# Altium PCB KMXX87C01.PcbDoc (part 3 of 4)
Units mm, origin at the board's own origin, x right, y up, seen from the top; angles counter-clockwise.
Board outline 109.2 x 85.1 mm, 4 copper layers (Top Layer, Mid-Layer 1, Mid-Layer 2, Bottom Layer); 294 components, 222 nets, 951 pads, 352 vias.
Unrouted connection lines stored in the file: 266.
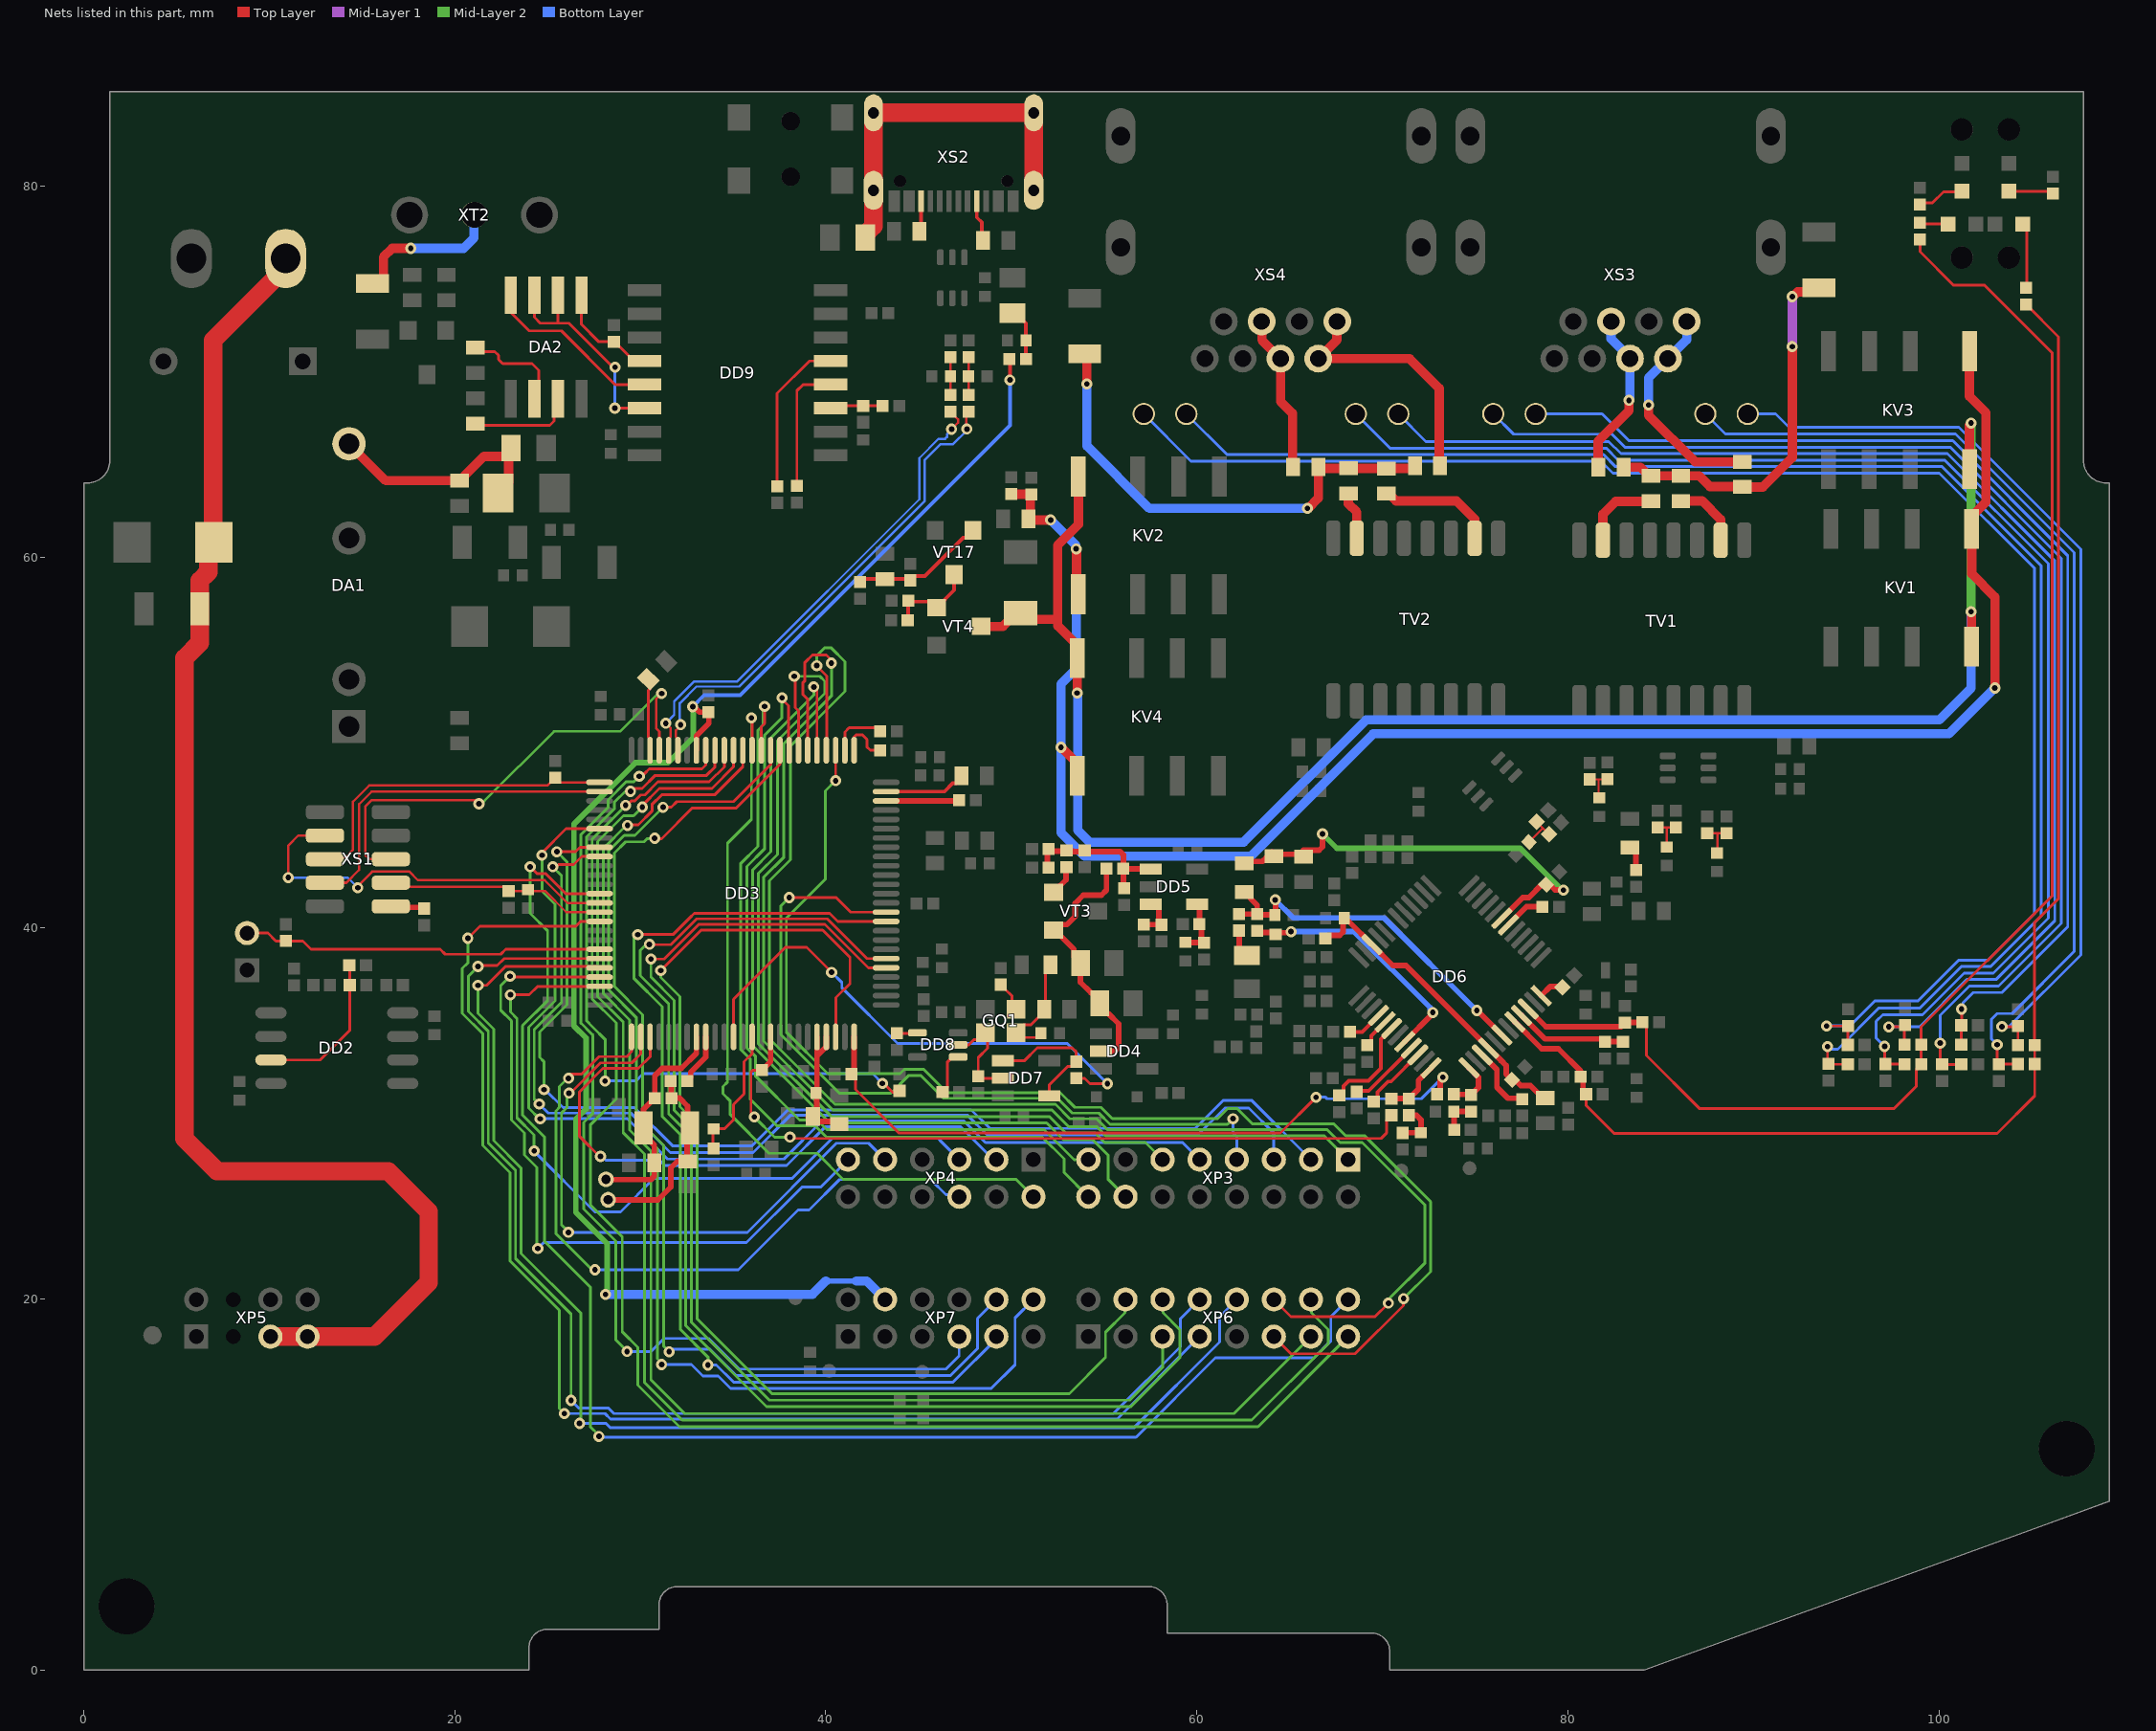
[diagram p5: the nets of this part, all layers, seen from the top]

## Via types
v1: diameter 0.6, hole 0.3, Top Layer to Bottom Layer, tented both sides, 292 vias
v2: diameter 0.6, hole 0.3, Top Layer to Bottom Layer, 60 vias

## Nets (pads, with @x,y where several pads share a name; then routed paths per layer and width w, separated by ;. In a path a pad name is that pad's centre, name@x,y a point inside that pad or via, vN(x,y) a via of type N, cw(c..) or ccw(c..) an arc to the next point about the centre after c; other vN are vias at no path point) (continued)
JTCK-SWCLK: DD3.76 R7.2 XS1.6 | length 18.2
  Top Layer w0.13: XS1.6@13,43.715 13.081,43.796 14.09,43.796 14.509,44.215 14.509,46.815 15.381,47.687 24.994,47.687 R7.2@25.407,48.1 25.649,47.857 DD3.76@27.8,47.857
JTDI: DD3.77 XS1.4 | length 18.9
  Top Layer w0.13: XS1.4@13,42.445 14.145,42.445 14.839,43.139 14.839,46.679 15.518,47.357 DD3.77@27.8,47.357
JTDO/SWO: DD3.89 XS1.8 | length 22
  Top Layer w0.13: v1(11.025,42.725) 11.025,44.45 11.56,44.985 XS1.8@13,44.985 ; v1(14.77,42.175) 14.77,42.263 15.547,43.04 17.553,43.04 18.007,42.585 24.841,42.585 26.085,41.341 27.784,41.341 DD3.89@27.8,41.357
  Bottom Layer w0.13: v1(11.025,42.725) 14.22,42.725 v1(14.77,42.175)
JTMS-SWDIO: DD3.72 XS1.5 | length 26
  Top Layer w0.13: XS1.5@16.55,43.715 15.385,43.715 15.169,43.931 15.169,46.542 15.527,46.9 21.1,46.9 v1(21.3,46.7) ; DD3.72@31.025,49.582 31.025,50.593 30.861,50.757 30.861,52.361 v1(31.15,52.65)
  Mid-Layer 2 w0.13: v1(21.3,46.7) 21.427,46.7 21.572,46.845 21.595,46.845 25.35,50.6 28.912,50.6 30.872,52.56 31.06,52.56 v1(31.15,52.65)
MDC: DD3.16 R12.1 R270.2 | length 40.6
  Top Layer w0.15: v1@35.965,29.964 35.965,32.243 36.061,32.34 R12.1@36.565,32.34 ; v1@38.063,28.66 69.929,28.66 70.241,28.971 70.241,29.661 R270.2@70.487,29.907
  Top Layer w0.3: R12.1@36.565,32.34 37.025,32.801 DD3.16@37.025,34.132
  Mid-Layer 2 w0.15: v1(36.145,29.816) 37.233,28.728 v1(38.063,28.728)
MDIO: DD3.25 R11.1 R271.2 | length 37.5
  Top Layer w0.15: R11.1@41.375,32.125 41.598,31.903 41.598,31.297 43.935,28.96 64.505,28.96 v1(66.424,30.879)
  Top Layer w0.3: 41.525,32.495 DD3.25@41.525,34.132 ; R271.2@72.954,31.046 73.121,31.214 73.121,31.823 v1(73.263,31.964)
  Bottom Layer w0.15: v1(66.424,30.879) 66.938,30.879 67.018,30.8 72.099,30.8 v1(73.263,31.964)
NetBQ1_1: BQ1.1 BQ2.2 C8.1 R16.2 R329.2 | length 10.7
  Top Layer w0.3: BQ2.2@28.265,25.35 30.944,25.35 31.639,26.045 31.639,27.069 32,27.43 C8.1@32.3,27.43 ; R16.2@31.675,31.758 R329.2@31.675,30.833 32.117,30.833 32.551,30.399 32.551,29.31 32.655,29.205 BQ1.1@32.764,29.096 ; C8.1@32.525,27.503 32.525,29.075 BQ1.1@32.675,29.225
NetBQ1_2: BQ1.2 BQ2.1 C7.1 DD3.8 R329.1 | length 12.3
  Top Layer w0.3: BQ2.1@28.15,26.454 28.164,26.44 30.574,26.44 30.75,26.616 C7.1@30.75,27.347 ; C7.1@30.755,27.35 30.75,27.355 30.75,28.299 30.574,28.475 30.523,28.475 30.173,28.825 30.173,30.231 30.6,30.658 R329.1@30.775,30.833 30.775,32.038 31.169,32.433 32.208,32.433 33.025,33.25 DD3.8@33.025,34.132
NetC11_1: C11.1 DA1.7 L5.1 L6.1 | length 12.3
  Top Layer w0.5: DA1.7@14.291,66.107 16.276,64.122 C11.1@20.262,64.122 ; C11.1@20.512,64.372 21.566,65.425 22.457,65.425 22.75,65.425 22.787,65.463 22.787,65.638 L5.1@23.025,65.875 ; L6.1@22.326,63.45 22.9,64.024 L5.1@22.9,65.525
NetC17_1: C17.1 DD3.73 | length 4
  Top Layer w0.15: C17.1@30.437,53.46 30.52,53.377 30.52,52.907 30.437,52.824 30.437,50.286 30.525,50.198 DD3.73@30.525,49.582
NetC19_1: C19.1 C22.1 DD3.21 DD3.22 L1.1 | length 7.4
  Top Layer w0.3: C22.1@39.046,29.8 C22.1@39.191,29.945 ; C22.1@39.096,29.75 39.271,29.575 40.307,29.575 L1.1@40.468,29.414 ; C22.1@39.305,29.85 39.513,30.058 39.513,31.062 C19.1@39.475,31.1 39.525,31.15 39.525,33.11 ; DD3.21@39.525,34.132 39.525,33.11 ; DD3.22@40.025,34.132 40.025,33.557 39.973,33.557 39.525,33.11
NetC20_1: C20.1 DD3.49 | length 4.5
  Top Layer w0.2: DD3.49@43.25,47.357 46.395,47.357 46.841,47.804 47.041,47.804 47.316,48.079 C20.1@47.316,48.204
NetC33_1: C33.1 DD3.14 R35.1 | length 7.2
  Top Layer w0.15: C33.1@33.92,29.154 33.92,28.149 R35.1@33.95,28.119 ; C33.1@33.954,29.178 34.537,29.178 35.02,29.66 35.02,30.485 35.596,31.062 35.596,32.796 36.025,33.225 DD3.14@36.025,34.132
NetC36_1: C36.1 DD5.4 R28.2 R33.1 | length 3.1
  Top Layer w0.3: C36.1@59.376,39.225 59.382,39.219 R28.2@60.25,39.219 ; DD5.4@60.016,41.282 60.141,41.157 R33.1@60.141,40.206 60.25,40.097 60.25,39.35 R28.2@60.4,39.2
NetC41_2: C41.2 C150.2 DD4.2 R45.2 VT3.2 | length 13.3
  Top Layer w0.3: C41.2@54.288,36.519 53.729,37.078 C150.2@53.729,38.104 53.371,38.462 53.371,38.856 52.639,39.588 52.332,39.895 VT3.2@52.281,39.895 52.569,40.183 52.995,40.183 53.447,40.635 53.447,41.339 53.878,41.771 54.857,41.771 55.125,42.039 R45.2@55.125,43.207 ; C41.2@54.76,35.746 55.118,35.388 55.237,35.388 55.785,34.84 55.785,33.539 55.609,33.363 DD4.2@54.835,33.363
NetC45_1: C45.1 C47.1 C171.1 DD6.22 DD6.40 R70.2 | length 17.1
  Top Layer w0.3: R70.2@66.929,39.436 67.104,39.611 67.708,39.611 67.884,39.786 67.884,40.477 C45.1@67.943,40.537 67.943,40.512 68.093,40.362 68.192,40.362 DD6.22@69.443,39.111 70.569,37.984 71.276,37.984 72.104,37.156 DD6.40@75.736,33.525 76.403,32.857 76.676,32.585 76.676,32.12 C47.1@76.983,31.813 77.157,31.813 77.462,31.507 77.985,31.507 78.655,30.837 C171.1@78.881,30.837
NetC46_1: C46.1 C48.1 C170.1 DD6.7 L2.1 | length 23.6
  Top Layer w0.3: L2.1@62.55,43.59 63.538,43.59 63.736,43.788 63.803,43.788 64.057,44.041 C170.1@64.057,44.109 ; C170.1@64.153,44.013 64.186,43.98 C46.1@65.746,43.98 ; C46.1@65.746,44.205 66.599,44.205 66.775,44.381 v1(66.775,45.075) ; DD6.7@76.443,40.525 77.568,41.65 77.903,41.65 78.604,42.35 78.816,42.35 C48.1@78.829,42.337 79.033,42.337 79.314,42.057 79.754,42.057 v1(79.764,42.046)
  Mid-Layer 2 w0.3: v1(66.775,45.075) 67.544,44.306 77.435,44.306 79.695,42.046 v1(79.764,42.046)
NetC51_1: C51.1 DD6.42 L2.2 R64.1 R73.1 | length 19.8
  Top Layer w0.3: R73.1@62.28,40.764 62.287,40.757 63.243,40.757 R64.1@63.25,40.75 ; L2.2@62.475,42.012 62.704,42.012 62.9,41.815 62.9,41.587 63.25,41.237 R64.1@63.25,40.75 ; v1(64.227,41.522) 64.243,41.506 64.243,40.734 C51.1@64.202,40.693 64.174,40.722 63.278,40.722 R64.1@63.25,40.75 ; v1(75.092,35.555) 75.12,35.555 DD6.42@76.443,34.232
  Bottom Layer w0.3: v1(64.227,41.522) 65.199,40.55 70.089,40.55 75.084,35.555 v1(75.092,35.555)
NetC52_2: C52.2 R73.2 | length 1.6
  Top Layer w0.3: R73.2@62.28,39.864 62.28,38.882 62.638,38.524 C52.2@62.7,38.524
NetC53_1: C53.1 R92.2 R93.2 | length 2
  Top Layer w0.127: C53.1@77.904,44.645 78.625,45.367 78.625,45.409 ; R92.2@78.31,45.724 78.625,45.409 ; R93.2@78.986,45.056 78.978,45.056 78.625,45.409
NetC54_1: C54.1 R94.2 R95.2 | length 2
  Top Layer w0.127: R94.2@81.183,48.016 81.658,48.016 ; C54.1@81.689,47.024 81.658,47.056 81.658,48.016 ; R95.2@82.139,48.029 82.125,48.016 81.658,48.016
NetC55_1: C55.1 R88.2 R89.2 | length 2
  Top Layer w0.127: R88.2@84.851,45.43 84.852,45.428 85.345,45.428 ; C55.1@85.331,44.372 85.331,45.414 85.345,45.428 ; R89.2@85.82,45.428 85.345,45.428
NetC56_1: C56.1 R90.2 R91.2 | length 2.1
  Top Layer w0.127: R90.2@87.514,45.11 88.06,45.11 ; C56.1@88.035,44.046 88.06,44.071 88.06,45.11 ; R91.2@88.559,45.11 88.06,45.11
NetC61_1: C61.1 KV1.1 KV2.1 KV3.1 KV4.1 R102.2 R103.2 | length 100.5
  Top Layer w0.5: R102.2@50,63.4 50.01,63.39 51.063,63.39 R103.2@51.072,63.381 51.025,63.333 51.025,62.152 C61.1@50.924,62.051 50.975,62 v2(52.12,62) ; v2(52.675,49.747) 52.689,49.747 53.557,48.879 KV4.1@53.557,48.204 ; v2(53.496,60.441) 53.515,60.422 53.515,58.098 KV2.1@53.617,57.995 KV2.1@53.617,57.32 ; KV3.1@101.65,71.1 101.65,68.666 102.545,67.771 102.545,62.969 101.775,62.199 KV1.1@101.775,61.524 101.775,59.1 103.025,57.85 v2@103.025,52.95
  Bottom Layer w0.5: v2(52.12,62) 53.477,60.643 53.477,60.46 v2(53.496,60.441) 53.496,53.971 52.675,53.15 v2(52.675,49.747) 52.675,45.15 53.95,43.875 62.9,43.875 69.5,50.475 100.55,50.475 v2(103.021,52.946)
NetC62_1: C62.1 R25.1 R40.1 R98.1 R99.1 | length 20.5
  Top Layer w0.5: R25.1@83.005,64.85 83.901,64.85 84.364,64.386 R98.1@84.489,64.386 R99.1@86.095,64.386 87.074,64.386 87.66,63.8 R40.1@89.403,63.8 ; R40.1@89.4,63.777 89.403,63.78 90.51,63.78 92.1,65.37 v2(92.1,71.35) ; v2(92.1,74.044) 92.127,74.044 92.386,74.303 93.309,74.303 C62.1@93.525,74.519
  Mid-Layer 1 w0.5: v2(92.1,71.35) v2(92.1,74.044)
NetC63_1: C63.1 R100.1 R101.1 R106.1 R107.1 | length 25.6
  Top Layer w0.5: C63.1@53.954,70.957 54.072,70.84 v2(54.072,69.338) ; v2@66,62.625 66.553,63.178 R106.1@66.553,64.86 66.627,64.786 R100.1@68.172,64.786 68.176,64.782 70.22,64.782 R101.1@70.223,64.778 R107.1@71.389,64.778
  Bottom Layer w0.5: v2(54.072,69.338) 54.072,65.998 57.445,62.625 v2(65.96,62.625)
NetC67_2: C67.2 VD5.1 XP1.1 XP5.5 XP5.7 | length 79.1
  Top Layer w1: XP5.5@10.06,17.976 XP5.7@12.06,17.976 15.677,17.976 18.592,20.891 18.592,24.709 16.411,26.89 7.184,26.89 5.425,28.649 5.425,54.55 6.243,55.368 6.243,57.192 C67.2@6.251,57.2 6.251,58.734 6.708,59.192 6.708,60.495 VD5.1@7.005,60.792 6.975,60.822 6.975,71.695 10.88,75.6 XP1.1@10.88,76.1
  Mid-Layer 1 w1: XP1.1@10.88,75.6 XP1.1@10.88,76.1
  Mid-Layer 2 w2: XP1.1@10.88,75.546 XP1.1@10.88,76.1
NetC74_1: C74.1 L8.2 R8.1 | length 3.1
  Top Layer w0.2: L8.2@49.894,73.158 L8.2@50.069,73.158 50.244,73.158 50.789,72.613 C74.1@50.789,71.672 C74.1@50.789,71.622 ; C74.1@50.714,71.622 C74.1@50.789,71.622 ; R8.1@50.789,70.677 C74.1@50.789,71.622
NetC75_2: C75.2 R3.1 R380.2 | length 2
  Top Layer w0.127: R3.1@47.69,68.738 C75.2@47.69,69.738 R380.2@47.69,70.788
NetC76_2: C76.2 R10.1 R381.2 | length 2
  Top Layer w0.127: R10.1@46.715,68.738 C76.2@46.715,69.738 R381.2@46.715,70.788
NetC102_1: C102.1 R34.2 R322.1 VT17.1 | length 7.4
  Top Layer w0.2: R34.2@41.792,58.714 R34.2@41.847,58.659 ; R34.2@41.811,58.815 C102.1@43.181,58.815 44.481,58.815 R322.1@44.551,58.745 44.776,58.97 45.337,58.97 47.403,61.036 47.574,61.036 47.931,61.393 VT17.1@47.931,61.444
NetC120_1: C120.1 C146.1 GQ1.4 L11.2 | length 6.2
  Top Layer w0.15: C120.1@51.6,34.328 51.6,34.325 51.375,34.1 50.518,34.1 GQ1.4@50.25,34.368 50.675,34.793 51.063,34.793 51.77,35.5 C146.1@51.77,35.625 51.83,35.685 51.83,37.728 L11.2@52.12,38.018
NetC122_1: C122.1 R268.1 R383.2 | length 2.4
  Top Layer w0.3: R268.1@71.091,28.956 71.099,28.964 72.074,28.964 C122.1@72.081,28.971 72.081,29.668 71.842,29.907 R383.2@71.437,29.907
NetC124_1: C124.1 R269.1 R400.2 | length 1.9
  Top Layer w0.3: R269.1@73.872,29.132 73.867,29.137 73.867,30.103 C124.1@73.862,30.107 R400.2@74.793,30.109
NetC125_1: C125.1 DD6.32 R64.2 | length 13.7
  Top Layer w0.3: R64.2@63.2,39.864 63.306,39.758 64.15,39.758 C125.1@64.249,39.66 64.338,39.749 65.021,39.749 v1(65.08,39.808) ; DD6.32@71.21,33.878 72.723,35.391 v1(72.723,35.45)
  Bottom Layer w0.3: v1(65.08,39.808) 65.081,39.807 68.484,39.807 72.581,35.709 72.581,35.614 72.723,35.472 v1(72.723,35.45)
NetDA2_1: DA2.1 DD9.12 R17.1 | length 6
  Top Layer w0.15: DA2.1@26.83,74.344 26.83,72.542 27.763,71.609 R17.1@28.575,71.609 28.825,71.359 28.87,71.359 29.656,70.573 DD9.12@30.234,70.573
NetDA2_2: DA2.2 DA2.3 DD9.14 | length 12.3
  Top Layer w0.15: DA2.3@24.29,74.344 24.29,72.93 24.607,72.613 25.56,72.613 ; DA2.2@25.56,74.344 25.56,72.613 ; v2@28.546,70.278 28.484,70.278 26.149,72.613 25.56,72.613 ; v2(28.624,68.033) DD9.14@30.234,68.033
  Bottom Layer w0.15: v2(28.624,68.033) 28.629,68.039 28.629,70.235 v2(28.635,70.241)
NetDA2_4: DA2.4 DD9.13 | length 10
  Top Layer w0.15: DA2.4@23.02,74.344 23.02,73.183 24.003,72.2 25.745,72.2 28.642,69.303 DD9.13@30.234,69.303
NetDA2_6: DA2.6 R26.2 | length 5.7
  Top Layer w0.15: R26.2@21.106,71.299 21.33,71.075 22.158,71.075 22.354,70.879 22.354,70.653 22.582,70.425 24.166,70.425 24.525,70.066 24.525,68.766 DA2.6@24.29,68.531
NetDA2_7: DA2.7 R18.2 | length 5.7
  Top Layer w0.15: R18.2@21.1,67.205 21.205,67.1 25.117,67.1 25.35,67.333 25.35,68.321 DA2.7@25.56,68.531
NetDD2_7: DD2.7 R326.1 R327.2 | length 8.4
  Top Layer w0.15: DD2.7@10.09,32.889 12.739,32.889 14.336,34.486 R326.1@14.336,36.925 14.336,37.975 R327.2@14.311,38
NetDD3_9: DD3.9 R16.1 | length 2.8
  Top Layer w0.3: R16.1@32.539,31.758 32.714,31.933 32.714,32.229 33.525,33.04 DD3.9@33.525,34.132
NetDD3_12: DD3.12 R169.1 | length 28.3
  Top Layer w0.15: DD3.12@35.025,34.132 35.025,36.159 37.822,38.956 38.972,38.956 v1(40.311,37.617) ; R169.1@53.5,31.9 53.95,31.9 54.237,31.613 v1(55.177,31.613)
  Bottom Layer w0.15: v1(40.311,37.617) 40.864,37.064 40.864,36.786 43.875,33.775 53.016,33.775 v1(55.177,31.613)
NetDD3_48: DD3.48 R200.1 | length 3.9
  Top Layer w0.3: DD3.48@43.25,46.857 47.149,46.857 R200.1@47.183,46.892
NetDD3_51: DD3.51 R201.1 | length 2.8
  Top Layer w0.15: DD3.51@41.525,49.582 41.525,50.3 41.65,50.425 41.966,50.425 42.225,50.166 42.225,49.757 42.4,49.582 R201.1@42.92,49.582
NetDD3_52: DD3.52 R202.1 | length 3.1
  Top Layer w0.15: DD3.52@41.025,49.582 41.025,50.575 41.257,50.807 42.722,50.807 R202.1@42.929,50.6
NetDD3_66: DD3.66 R317.1 | length 39.8
  Top Layer w0.15: v1(29.47,47.372) 29.47,47.439 29.558,47.527 30.1,47.527 30.805,48.232 33.568,48.232 34.025,48.689 DD3.66@34.025,49.582 ; v2(43.05,31.625) 43.128,31.625 43.614,31.139 R317.1@43.99,31.139
  Mid-Layer 2 w0.15: v1(28.1,31.758) 28.1,33.999 27.447,34.652 27.1,34.999 27.1,44.917 28.592,46.409 28.592,46.782 29.264,47.453 29.335,47.382 29.46,47.382 v1(29.47,47.372)
  Bottom Layer w0.15: v1(28.1,31.758) 29.759,31.758 30.151,32.15 42.525,32.15 v2(43.05,31.625)
NetDD3_94: DD3.94 R20.1 XP2.2 | length 19.6
  Top Layer w0.15: XP2.2@8.8,39.729 9.928,39.729 10.356,39.302 R20.1@10.9,39.302 11.806,39.302 12.25,38.857 19.213,38.857 19.482,38.588 22.472,38.588 22.741,38.857 DD3.94@27.8,38.857
NetDD5_1: DD5.1 R44.2 R45.1 R46.1 R47.2 R48.2 R328.2 | length 8.4
  Top Layer w0.3: R44.2@51.964,43.229 51.945,43.248 51.945,44.154 51.948,44.151 52.976,44.151 53.342,44.151 53.364,44.129 53.954,44.129 55.862,44.129 56.038,43.954 R45.1@56.038,43.195 ; R328.2@56.075,42.15 56.05,42.175 56.05,43.182 R45.1@56.038,43.195 ; DD5.1@57.516,43.182 57.504,43.195 R45.1@56.038,43.195
NetDD5_3: DD5.3 R30.2 R41.1 | length 2.5
  Top Layer w0.3: R30.2@57.147,40.186 57.975,40.186 58.122,40.186 58.114,40.186 57.95,40.35 57.95,41.132 57.8,41.282 DD5.3@57.516,41.282
NetDD6_6: DD6.6 R65.1 | length 2.2
  Top Layer w0.3: DD6.6@76.797,40.171 77.775,41.15 R65.1@78.625,41.15
NetDD6_28: DD6.28 R233.1 | length 1.9
  Top Layer w0.2: R233.1@68.25,34.404 68.908,34.404 DD6.28@69.796,35.292
NetDD6_29: DD6.29 R234.1 | length 1.7
  Top Layer w0.2: R234.1@69.183,33.684 69.408,33.909 69.408,34.197 DD6.29@70.15,34.939
NetDD6_30: DD6.30 R51.1 | length 5.4
  Top Layer w0.2: R51.1@67.679,30.971 67.904,31.196 67.904,31.479 68.198,31.773 69.256,31.773 69.925,32.442 69.925,34.007 DD6.30@70.503,34.585
NetDD6_33: DD6.33 R50.1 | length 3.9
  Top Layer w0.2: R50.1@68.61,31.175 68.66,31.225 69.264,31.225 DD6.33@71.564,33.525
NetDD6_34: DD6.34 R321.1 | length 3.6
  Top Layer w0.2: R321.1@69.537,30.65 69.735,30.848 69.735,31.161 70.304,31.73 70.476,31.73 DD6.34@71.917,33.171
NetDD6_36: DD6.36 R270.1 R383.1 | length 3.1
  Top Layer w0.3: R270.1@70.487,30.807 R383.1@71.437,30.807 71.948,31.319 71.948,31.788 DD6.36@72.625,32.464
NetDD6_37: DD6.37 R271.1 R400.1 | length 2.8
  Top Layer w0.3: R271.1@73.854,31.046 73.872,31.027 74.774,31.027 R400.1@74.793,31.009 75.176,31.392 75.176,31.963 DD6.37@74.675,32.464
NetDD6_39: DD6.39 R67.2 | length 3.7
  Top Layer w0.3: DD6.39@75.382,33.171 76.176,32.377 76.176,31.419 76.774,30.82 77.499,30.82 R67.2@77.537,30.782
NetDD6_48: DD6.48 R68.2 | length 1.4
  Top Layer w0.3: DD6.48@78.564,36.353 79.067,36.855 79.411,36.855 79.639,36.627 R68.2@79.658,36.627
NetDD7_1: DD7.1 DD7.4 R169.2 | length 7.4
  Top Layer w0.15: DD7.1@49.634,32.84 50.695,32.84 51.405,33.55 53.272,33.55 53.5,33.322 R169.2@53.5,32.8 53.25,32.55 53.05,32.55 52.05,31.55 DD7.4@52.05,30.95 ; DD7.4@52.134,30.94 DD7.4@52.134,30.95
NetDD7_2: DD7.2 DD8.2 GQ1.3 R357.2 | length 5.8
  Top Layer w0.15: DD8.2@47.138,33.704 47.704,33.704 47.975,33.975 48.27,33.975 GQ1.3@48.483,34.188 ; GQ1.3@48.483,34.25 GQ1.3@48.6,34.368 48.725,34.243 48.725,33.521 48.217,33.013 R357.2@48.217,32.002 48.328,31.89 DD7.2@49.634,31.89
NetDD8_1: DD8.1 R378.1 | length 2.4
  Top Layer w0.15: R378.1@46.294,31.157 46.544,31.407 46.544,32.76 46.838,33.054 DD8.1@47.138,33.054
NetDD8_4: DD8.4 R358.2 | length 1.3
  Top Layer w0.15: R358.2@43.835,34.328 DD8.4@45.117,34.328
NetDD9_3: DD9.3 R4.2 R15.2 | length 2.8
  Top Layer w0.15: DD9.3@40.267,68.033 40.39,68.156 R15.2@42.015,68.156 R4.2@43.05,68.156
NetDD9_4: DD9.4 R5.2 | length 7.1
  Top Layer w0.15: R5.2@38.441,63.835 38.441,68.97 38.774,69.303 DD9.4@40.267,69.303
NetDD9_5: DD9.5 R6.2 | length 8.6
  Top Layer w0.15: R6.2@37.375,63.825 37.375,68.825 39.123,70.573 DD9.5@40.267,70.573
NetGQ1_1: GQ1.1 R167.1 | length 1.7
  Top Layer w0.15: R167.1@49.425,36.95 49.675,36.7 50.025,36.35 50.025,35.843 GQ1.1@50.25,35.618
NetHL1_C: HL1.C R38.2 | length 2.4
  Top Layer w0.15: HL1.C@103.779,79.726 106.031,79.726 R38.2@106.15,79.607
NetHL2_C: HL2.C R37.1 | length 2.4
  Top Layer w0.15: R37.1@99.082,79.107 99.665,79.107 100.248,79.69 101.203,79.69 HL2.C@101.239,79.726
NetHL15_C: HL15.C R74.2 | length 3.6
  Top Layer w0.15: HL15.C@104.529,77.956 104.75,77.735 104.75,74.55 R74.2@104.65,74.45
NetHL16_C: HL16.C R75.2 | length 1.5
  Top Layer w0.15: R75.2@98.983,78.025 99.052,77.956 HL16.C@100.489,77.956
NetKV1_8: KV1.8 KV2.8 KV3.8 KV4.8 VD8.2 VT4.3 | length 96.5
  Top Layer w0.5: VT4.3@48.363,56.265 49.54,56.265 50.25,56.975 VD8.2@50.5,56.975 50.825,56.65 52.498,56.65 ; v2(53.55,52.673) 53.554,52.677 53.554,54.55 KV4.8@53.557,54.554 53.557,55.229 52.498,56.288 52.498,56.65 ; KV2.8@53.617,64.345 53.617,61.767 52.498,60.648 52.498,56.65 ; KV3.8@101.65,64.075 KV3.8@101.65,64.75 101.65,67.109 101.739,67.198 v2(101.739,67.225) ; v2(101.739,57.057) 101.757,57.039 101.757,55.192 KV1.8@101.775,55.174 KV1.8@101.775,54.499
  Mid-Layer 2 w0.5: v2(101.739,57.057) v2(101.739,67.225)
  Bottom Layer w0.5: v2@53.575,52.725 53.575,45.275 54.225,44.625 62.525,44.625 69.125,51.225 100.025,51.225 101.739,52.939 v2(101.739,57.057)
NetL3_1: L3.1 R72.2 | length 1.4
  Top Layer w0.3: L3.1@83.35,44.35 83.45,44.35 83.675,44.125 R72.2@83.675,43.125
NetL4_1: L4.1 XS2.SHELL | length 19.7
  Top Layer w1: L4.1@42.125,77.225 42.125,77.4 42.57,77.845 XS2.SHELL@42.57,79.77 XS2.SHELL@42.57,83.95 XS2.SHELL@51.21,83.95 XS2.SHELL@51.21,79.77
NetR1_1: R1.1 XS2.A5 | length 2.3
  Top Layer w0.2: XS2.A5@48.14,79.195 48.14,78.313 48.403,78.05 48.403,77.154 R1.1@48.475,77.082
NetR2_1: R2.1 XS1.1 | length 1.9
  Top Layer w0.3: XS1.1@16.55,41.175 16.612,41.112 18.288,41.112 R2.1@18.35,41.05
NetR23_1: R23.1 XS2.B5 | length 1.7
  Top Layer w0.2: R23.1@45.045,77.563 45.14,77.658 XS2.B5@45.14,79.195
NetR25_2: R25.2 XS3.4 XS3.5 | length 8
  Top Layer w0.5: R25.2@81.645,64.85 81.635,64.86 81.635,66.24 83.3,67.905 v2(83.3,68.45)
  Bottom Layer w0.5: XS3.4@82.33,72.202 82.33,71.77 83.35,70.75 XS3.5@83.35,70.7 ; v2(83.3,68.45) 83.35,68.5 XS3.5@83.35,70.202
NetR40_2: R40.2 XS3.7 XS3.8 | length 11.2
  Top Layer w0.5: v2(84.35,68.202) 84.35,67.643 86.856,65.137 R40.2@89.4,65.137
  Bottom Layer w0.5: v2(84.35,68.202) 84.35,69.66 XS3.7@85.39,70.7 ; XS3.7@85.689,70.864 85.689,70.999 86.41,71.72 XS3.8@86.41,72.202
NetR42_2: R42.2 R43.2 XS3.9 | length 50.6
  Top Layer w0.15: v1(103.4,34.687) 104.236,34.687 R42.2@104.265,34.716 ; R43.2@104.265,33.689 R42.2@104.265,34.716 ; R42.2@104.268,34.719 R42.2@104.265,34.716
  Bottom Layer w0.15: XS3.9@89.7,67.72 91.194,67.72 91.919,66.995 101.08,66.995 107.65,60.425 107.65,38.55 103.777,34.677 v1@103.4,34.677
NetR46_2: R46.2 VT3.1 | length 1.8
  Top Layer w0.3: VT3.1@52.281,41.927 52.332,41.927 52.639,42.235 52.639,42.285 52.948,42.594 52.948,43.256 R46.2@52.976,43.285 ; R46.2@52.867,43.175 R46.2@52.942,43.25
NetR66_2: R66.2 R69.2 XS3.10 | length 54.1
  Top Layer w0.15: v1(103.145,33.711) 103.145,32.739 R66.2@103.225,32.659 104.258,32.659 R69.2@104.268,32.669
  Bottom Layer w0.15: XS3.10@87.41,67.72 88.485,66.645 100.905,66.645 107.3,60.25 107.3,38.74 103.953,35.393 103.145,35.393 102.825,35.073 102.825,34.031 v1(103.145,33.711)
NetR86_2: R86.2 R87.2 XS3.11 | length 61.7
  Top Layer w0.15: v1(101.225,35.632) 101.225,34.774 R86.2@101.212,34.761 R87.2@101.212,33.711 ; R87.2@101.212,33.711 101.212,33.625 R87.2@101.212,33.711
  Bottom Layer w0.15: XS3.11@78.27,67.72 81.848,67.72 83.293,66.275 100.755,66.275 106.95,60.08 106.95,40.069 103.406,36.525 101.859,36.525 101.298,35.964 101.298,35.705 v1(101.225,35.632)
NetR96_1: R96.1 R97.1 VT4.1 VT17.3 | length 5.3
  Top Layer w0.2: R97.1@44.412,56.597 44.441,56.626 R96.1@44.441,57.65 44.491,57.6 45.657,57.6 VT4.1@45.976,57.281 46.915,58.22 VT17.3@46.915,59.431
NetR98_2: R98.2 TV1.15 | length 4.4
  Top Layer w0.5: TV1.15@81.929,60.954 TV1.15@81.89,60.915 81.89,62.312 82.579,63 84.363,63 84.413,62.95 R98.2@84.489,63.026
NetR99_2: R99.2 TV1.10 | length 3.7
  Top Layer w0.5: R99.2@86.095,63.026 87.249,63.026 88.24,62.035 TV1.10@88.24,60.915
NetR100_2: R100.2 TV2.15 | length 2.6
  Top Layer w0.5: R100.2@68.172,63.426 68.172,62.878 68.624,62.426 TV2.15@68.624,61.015
NetR101_2: R101.2 TV2.10 | length 6.4
  Top Layer w0.5: R101.2@70.223,63.418 70.348,63.418 70.74,63.026 73.999,63.026 74.974,62.051 TV2.10@74.974,61.015
NetR104_2: R104.2 R105.2 XS3.12 | length 65.8
  Top Layer w0.15: v1(100.078,33.8) 100.078,32.747 R104.2@100.175,32.65 101.201,32.65 R105.2@101.212,32.661
  Bottom Layer w0.15: XS3.12@75.98,67.72 77.075,66.625 82.381,66.625 83.081,65.925 100.61,65.925 106.6,59.935 106.6,40.247 103.228,36.875 101.655,36.875 100.078,35.298 v1(100.078,33.8)
NetR106_2: R106.2 XS4.4 XS4.5 | length 8.6
  Top Layer w0.5: XS4.4@63.491,72.7 63.511,72.68 63.511,71.7 XS4.5@64.511,70.7 64.511,68.395 65.16,67.745 65.16,64.892 R106.2@65.193,64.86
  Bottom Layer w0.5: XS4.5@64.511,70.7 XS4.5@64.511,70.75
NetR107_2: R107.2 XS4.7 XS4.8 | length 13.8
  Top Layer w0.5: XS4.8@67.571,72.7 67.551,72.68 67.551,71.7 XS4.7@66.551,70.7 71.466,70.7 73.069,69.097 73.069,64.962 R107.2@73.114,64.917
NetR108_2: R108.2 R109.2 XS4.9 | length 71.3
  Top Layer w0.15: v1(97.3,34.677) 98.086,34.677 R108.2@98.15,34.741 ; R109.2@98.15,33.716 R108.2@98.15,34.741 ; R108.2@98.175,34.766 R108.2@98.15,34.741
  Bottom Layer w0.15: XS4.9@70.861,67.72 72.347,66.234 82.204,66.234 82.863,65.575 100.465,65.575 106.25,59.79 106.25,40.392 103.083,37.225 101.51,37.225 98.962,34.677 v1(97.3,34.677)
NetR110_2: R110.2 R111.2 XS4.10 | length 74.9
  Top Layer w0.15: v1(97.075,33.625) 97.075,32.717 R110.2@97.125,32.667 97.134,32.659 R111.2@98.15,32.659
  Bottom Layer w0.15: XS4.10@68.571,67.72 70.416,65.875 82.068,65.875 82.718,65.225 100.32,65.225 105.9,59.645 105.9,40.537 102.938,37.575 101.365,37.575 99.115,35.325 96.975,35.325 96.625,34.975 96.625,34.075 v1(97.075,33.625)
NetR112_2: R112.2 R113.2 XS4.11 | length 84.9
  Top Layer w0.15: v1(94,33.606) 94,32.723 R112.2@94.05,32.673 94.066,32.656 R113.2@95.097,32.656
  Bottom Layer w0.15: XS4.11@59.431,67.72 61.626,65.525 81.923,65.525 82.573,64.875 100.175,64.875 105.515,59.535 105.515,40.647 102.793,37.925 101.22,37.925 98.982,35.687 96.762,35.687 94.55,33.475 v1@93.975,33.475
NetR114_2: R114.2 R115.2 XS4.12 | length 85.9
  Top Layer w0.15: v1(93.95,34.718) 95.095,34.718 R114.2@95.1,34.723 95.1,33.703 R115.2@95.097,33.7
  Bottom Layer w0.15: XS4.12@57.141,67.72 59.686,65.175 81.778,65.175 82.428,64.525 100.025,64.525 105.165,59.385 105.165,40.792 102.648,38.275 101.075,38.275 98.875,36.075 96.55,36.075 95.198,34.723 v1@94,34.723
NetR116_2: R116.2 XT2.2 | length 8.4
  Top Layer w0.5: R116.2@15.55,74.752 15.892,74.752 16.15,75.01 16.15,76.175 16.625,76.65 v2(17.625,76.65)
  Bottom Layer w0.5: v2(17.625,76.65) 20.475,76.65 21.026,77.201 21.026,78.417 XT2.2@21.06,78.451
NJTRST: C72.2 DD3.90 R39.1 XS1.3 | length 11.9
  Top Layer w0.13: XS1.3@16.55,42.445 16.77,42.225 22.88,42.225 23.115,41.99 24.153,41.99 24.876,41.99 26.008,40.857 DD3.90@27.8,40.857
OTG_FS_D_N: DD3.70 R3.2 | length 26.7
  Top Layer w0.127: DD3.70@32.025,49.582 32.025,50.204 31.913,50.316 31.913,50.654 32.172,50.912 v2(32.172,50.965) ; v2(47.602,66.903) 47.574,66.932 47.574,67.722 R3.2@47.69,67.838
  Bottom Layer w0.127: v2(32.172,50.965) 32.125,51.012 32.125,52.125 33.021,53.021 35.336,53.021 45.318,63.003 45.318,65.224 46.167,66.073 46.841,66.073 47.602,66.835 v2(47.602,66.903)
OTG_FS_D_P: DD3.71 R10.2 | length 26.7
  Top Layer w0.127: v2(31.376,51.041) 31.636,50.78 31.636,50.316 31.525,50.204 DD3.71@31.525,49.582 ; R10.2@46.715,67.838 47.125,67.428 47.125,67.242 v2(46.778,66.895)
  Bottom Layer w0.127: v2(31.376,51.041) 31.825,51.49 31.825,52.217 32.906,53.298 35.221,53.298 45.041,63.117 45.041,65.339 46.077,66.375 46.425,66.375 46.533,66.483 46.533,66.625 46.778,66.87 v2(46.778,66.895)
OTG_FS_VBUS: DD3.68 R8.2 R325.2 XP7.4 | length 82.7
  Top Layer w0.2: R8.2@49.889,70.677 49.925,70.641 v1(49.925,69.55)
  Top Layer w0.3: v1(32.825,51.938) 32.899,51.938 33.193,51.644 33.672,51.644 R325.2@33.675,51.642 33.693,51.624 33.693,51.032 33.025,50.365 DD3.68@33.025,49.582
  Mid-Layer 2 w0.3: v1(28.125,20.25) 28.125,20.275 28.206,20.356 28.206,22.995 26.525,24.676 26.525,29.703 27.074,30.252 27.074,34.07 26.425,34.719 26.425,45.6 29.737,48.913 31.488,48.913 32.85,50.275 32.85,51.913 v1(32.825,51.938)
  Bottom Layer w0.2: v1(32.825,51.938) 33.437,52.55 35.379,52.55 49.925,67.096 v1(49.925,69.55)
  Bottom Layer w0.3: 40.001,20.976 41.609,20.976 41.653,20.976
  Bottom Layer w0.5: v1(28.125,20.25) 39.275,20.25 40.001,20.976 ; 41.653,20.976 42.195,20.976 XP7.4@43.195,19.976
P1_Link_LED: DD6.44 R43.1 R69.1 R74.1 R77.2 R81.2 | length 76.2
  Top Layer w0.15: R81.2@80.985,31.046 80.985,30.44 82.493,28.932 103.145,28.932 105.168,30.956 R69.1@105.168,32.669 105.168,33.686 R43.1@105.165,33.689 105.165,40.297 106.45,41.582 106.45,71.875 R74.1@104.7,73.625
  Top Layer w0.3: DD6.44@77.15,34.939 78.593,33.496 79.494,33.496 80.693,32.297 R77.2@80.693,31.982 80.824,31.851 80.824,31.146 R81.2@80.962,31.007
P2_LED1: DD6.45 R79.2 R83.2 | length 6
  Top Layer w0.3: DD6.45@77.504,35.292 78.771,34.025 R79.2@82.029,34.025 ; R79.2@82,33.875 R83.2@82.975,33.875
P2_Link_LED: DD6.46 R75.1 R78.2 R82.2 R109.1 R111.1 | length 77.4
  Top Layer w0.15: R82.2@84.025,34.925 84.232,34.718 84.232,33.137 87.108,30.26 97.571,30.26 98.794,31.484 98.794,32.321 98.8,32.327 98.8,32.409 R111.1@99.05,32.659 R109.1@99.05,33.716 99.05,34.677 106.1,41.727 106.1,71.028 102.463,74.665 100.785,74.665 98.983,76.467 R75.1@98.983,77.125
  Top Layer w0.3: DD6.46@77.857,35.646 78.816,34.687 82.862,34.687 83.027,34.852 R78.2@83.075,34.852 ; R78.2@83.075,34.9 83.088,34.913 84.012,34.913 R82.2@84.025,34.925
PA0: DD3.23 XP6.4 | length 64
  Top Layer w0.15: v1(31.099,37.708) 31.099,37.717 33.278,39.895 39.83,39.895 41.303,38.422 41.303,37.003 40.548,36.248 40.548,34.156 DD3.23@40.525,34.132
  Mid-Layer 2 w0.15: v1(31.099,37.708) 31.099,37.331 32.129,36.301 32.129,30.374 33.052,29.45 33.052,18.948 37.1,14.9 53.125,14.9 55.078,16.853 55.078,18.209 56.12,19.251 56.12,19.943 XP6.4@56.153,19.976
PA5: DD3.30 XP6.5 | length 64.4
  Top Layer w0.15: v1(30.577,38.33) 31.288,38.33 33.153,40.195 39.954,40.195 42.292,37.857 DD3.30@43.25,37.857
  Mid-Layer 2 w0.15: v1(30.577,38.33) 30.574,38.327 30.574,37.361 31.829,36.106 31.829,30.179 32.752,29.255 32.752,18.753 36.955,14.55 56.375,14.55 58.153,16.328 XP6.5@58.153,17.976
PA6: DD3.31 XP6.6 | length 69.2
  Top Layer w0.15: v1(30.49,39.125) 30.518,39.125 30.54,39.103 31.637,39.103 33.029,40.495 40.078,40.495 42.216,38.357 DD3.31@43.25,38.357
  Mid-Layer 2 w0.15: v1(30.49,39.125) 30.366,39.125 30.353,39.138 30.237,39.023 30.224,39.023 29.999,38.798 29.999,37.441 31.527,35.913 31.527,29.986 32.452,29.06 32.452,18.558 36.81,14.2 56.449,14.2 59.078,16.829 59.078,18.359 58.186,19.251 58.186,19.943 XP6.6@58.153,19.976
PA8: DD3.67 XP7.7 | length 58.8
  Top Layer w0.15: v1(29.944,48.185) 30.066,48.185 30.217,48.336 30.236,48.336 30.482,48.582 33.325,48.582 33.525,48.782 DD3.67@33.525,49.582
  Mid-Layer 2 w0.15: v1(29.28,17.173) 29.28,17.195 28.675,17.8 28.675,23.127 26.95,24.852 26.95,29.527 27.449,30.026 27.449,34.226 27.322,34.352 26.839,34.835 26.824,34.85 26.8,34.874 26.8,45.041 28.265,46.506 28.265,46.909 29.252,47.897 29.656,47.897 v1(29.944,48.185)
  Bottom Layer w0.15: v1(29.28,17.173) 30.572,17.173 31.275,17.876 33.669,17.876 35.32,16.225 46.469,16.225 47.183,16.939 47.183,17.964 XP7.7@47.195,17.976
PB0: DD3.35 XP7.9 | length 56.1
  Top Layer w0.15: v1(29.863,39.65) 31.759,39.65 32.659,40.55 32.905,40.795 40.202,40.795 40.64,40.357 DD3.35@43.25,40.357
  Mid-Layer 2 w0.15: v1(29.863,39.65) 29.757,39.65 29.649,39.542 29.649,37.296 31.177,35.768 31.177,29.841 32.152,28.865 32.152,18.363 33.646,16.869 v1(33.646,16.446)
  Bottom Layer w0.15: v1(33.646,16.446) 34.094,16.446 35.015,15.525 46.865,15.525 49.195,17.855 XP7.9@49.195,17.976
PB1: DD3.36 XP3.7 | length 42.7
  Top Layer w0.15: v1(38.025,41.645) 40.555,41.645 41.343,40.857 DD3.36@43.25,40.857
  Mid-Layer 2 w0.15: v1(38.025,41.645) 37.575,41.195 37.575,34.259 40.734,31.1 43.51,31.1 44.45,32.04 45.128,32.04 46.343,30.825 52.489,30.825 53.289,30.025 54.717,30.025 55.317,29.425 61.65,29.425 v1(61.95,29.725)
  Bottom Layer w0.15: v1(61.95,29.725) 61.95,28.94 62.153,28.737 XP3.7@62.153,27.515
PB5: DD3.91 XP6.7 | length 71.8
  Top Layer w0.15: v1(20.701,39.452) 21.349,40.1 26.525,40.1 26.782,40.357 DD3.91@27.8,40.357
  Mid-Layer 2 w0.15: v1(20.701,39.452) 20.701,38.122 20.4,37.821 20.4,35.41 21.501,34.309 21.501,28.287 22.975,26.813 22.975,22.051 25.632,19.394 25.632,14.093 v1(25.9,13.825)
  Bottom Layer w0.15: v1@25.825,13.9 v1(25.9,13.825) 28.1,13.825 28.4,13.525 55.702,13.525 XP6.7@60.153,17.976
PB8: DD3.95 XP6.8 | length 70.2
  Top Layer w0.15: v1(21.251,37.929) 21.296,37.975 22.283,37.975 22.665,38.357 DD3.95@27.8,38.357
  Mid-Layer 2 w0.15: v1(21.251,37.929) 20.726,37.404 20.726,35.509 21.801,34.433 21.801,28.412 23.275,26.938 23.275,22.182 26.267,19.19 v1(26.267,14.535)
  Bottom Layer w0.15: v1(26.267,14.535) 26.677,14.125 28.275,14.125 28.575,13.825 55.507,13.825 59.113,17.431 59.113,18.936 XP6.8@60.153,19.976
PB9: DD3.96 XP6.10 | length 72.1
  Top Layer w0.15: v1(21.251,36.914) 21.714,36.914 22.727,37.927 27.731,37.927 DD3.96@27.8,37.857
  Mid-Layer 2 w0.15: v1(21.251,36.914) 21.251,35.408 22.101,34.558 22.101,28.536 23.575,27.062 23.575,22.461 26.792,19.244 26.792,13.367 v1(26.725,13.3)
  Bottom Layer w0.15: v1(26.725,13.3) 28.149,13.3 28.374,13.075 56.625,13.075 61.228,17.678 61.228,19.051 XP6.10@62.153,19.976
PB14: DD3.53 XP6.11 | length 70.2
  Top Layer w0.15: DD3.53@40.525,49.582 40.528,49.579 40.528,47.947 v1(40.532,47.943) ; XP6.11@64.153,17.976 65.078,17.051 68.536,17.051 71.135,19.65 71.135,20.01 v1(71.15,20.025)
  Mid-Layer 2 w0.15: v1@40.55,47.975 39.975,47.4 39.975,42.634 37.875,40.534 37.875,34.383 40.108,32.15 43.993,32.15 44.225,32.382 45.281,32.382 46.538,31.125 52.634,31.125 53.422,30.337 54.83,30.337 55.441,29.725 61.125,29.725 61.675,30.275 62.175,30.275 63.015,29.435 67.39,29.435 68.034,28.791 69.062,28.791 72.603,25.25 72.603,21.478 v1(71.15,20.025)
PB15: DD3.54 XP6.12 | length 81.4
  Top Layer w0.15: v1(39.513,54.15) 39.513,54.125 40.054,53.584 40.054,49.611 DD3.54@40.025,49.582 ; XP6.12@64.153,19.976 65.078,19.051 69.603,19.051 v1(70.328,19.776)
  Mid-Layer 2 w0.15: v1(39.513,54.15) 39.513,54.688 39.924,55.1 40.3,55.1 41.037,54.363 41.037,52.758 38.09,49.81 38.09,43.68 36.955,42.545 36.955,34.03 40.485,30.5 52.376,30.5 53.162,29.713 54.605,29.713 55.193,29.125 67.038,29.125 67.723,28.441 68.917,28.441 72.303,25.055 72.303,21.953 70.415,20.065 70.415,19.862 v1(70.328,19.776)
PC6: DD3.63 XP6.13 | length 78.2
  Top Layer w0.15: v1(29.308,45.535) 29.342,45.568 29.893,45.568 30.63,46.304 30.63,46.661 31.152,47.182 34.003,47.182 35.525,48.704 DD3.63@35.525,49.582
  Mid-Layer 2 w0.15: v1(29.308,45.535) 29.242,45.535 28,44.293 28,36.47 29.427,35.043 29.427,29.116 30.575,27.968 30.575,15.649 32.399,13.825 62.002,13.825 XP6.13@66.153,17.976
PC7: DD3.64 XP6.14 | length 82.3
  Top Layer w0.15: v1(30.105,46.522) 30.105,46.613 31.024,47.532 33.858,47.532 35.025,48.699 DD3.64@35.025,49.582
  Mid-Layer 2 w0.15: v1(30.105,46.522) 29.642,46.06 29.091,46.06 27.7,44.669 27.7,36.308 29.077,34.931 29.077,28.971 30.225,27.823 30.225,15.504 32.254,13.475 62.96,13.475 67.078,17.593 67.078,18.359 66.186,19.251 66.186,19.943 XP6.14@66.153,19.976
PC8: DD3.65 XP6.15 | length 82.5
  Top Layer w0.15: v1(29.202,46.618) 29.275,46.618 29.504,46.847 29.687,46.847 30.018,47.177 30.245,47.177 30.95,47.882 33.713,47.882 34.525,48.694 DD3.65@34.525,49.582
  Mid-Layer 2 w0.15: v1(29.202,46.618) 29.202,46.595 27.4,44.793 27.4,36.184 28.701,34.882 28.701,30.784 27.3,29.382 27.3,25.085 29.025,23.36 29.025,18.242 29.866,17.401 29.866,15.368 32.109,13.125 63.302,13.125 XP6.15@68.153,17.976
PD0: DD3.81 XP3.9 | length 57.3
  Top Layer w0.15: v1(24.7,43.925) 24.7,44.057 26,45.357 DD3.81@27.8,45.357
  Mid-Layer 2 w0.15: v1(24.601,29.716) 24.561,29.716 23.982,30.295 23.982,34.648 25.4,36.066 25.4,41.277 24.7,41.977 v1(24.7,43.925)
  Bottom Layer w0.15: v1(24.601,29.716) 24.61,29.725 29.295,29.725 31.47,27.55 37.745,27.55 39.795,29.6 47.447,29.6 48.607,28.441 59.228,28.441 XP3.9@60.153,27.515
PD2: DD3.83 XP3.3 | length 61.9
  Top Layer w0.15: v1(25.5,44.115) 26.518,44.115 26.76,44.357 DD3.83@27.8,44.357
  Mid-Layer 2 w0.15: v1(24.807,31.291) 24.8,31.297 24.8,32.806 24.582,33.025 24.582,34.4 26.05,35.868 26.05,43.565 v1(25.5,44.115)
  Bottom Layer w0.15: v1(24.807,31.291) 24.867,31.291 25.833,30.325 29.685,30.325 31.76,28.25 36.001,28.25 37.951,30.2 47.846,30.2 48.846,29.2 59.915,29.2 61.415,30.7 62.969,30.7 XP3.3@66.153,27.515
PD3: DD3.84 XP3.5 | length 61
  Top Layer w0.15: v1(25.276,43.302) 25.362,43.388 25.552,43.388 25.589,43.425 26.415,43.425 26.847,43.857 DD3.84@27.8,43.857
  Mid-Layer 2 w0.15: v1(24.55,30.515) 24.538,30.515 24.282,30.771 24.282,34.524 25.75,35.992 25.75,42.828 v1(25.276,43.302)
  Bottom Layer w0.15: v1(24.55,30.515) 24.55,30.51 25.035,30.025 29.49,30.025 31.615,27.9 36.075,27.9 38.075,29.9 47.65,29.9 48.7,28.85 60.06,28.85 61.51,30.3 62.8,30.3 64.153,28.947 XP3.5@64.153,27.515
PD7: DD3.88 XP6.16 | length 81.9
  Top Layer w0.15: v1(24.063,43.302) 24.44,42.925 24.911,42.925 25.978,41.857 DD3.88@27.8,41.857
  Mid-Layer 2 w0.15: v1(24.063,43.302) 24.063,40.787 25,39.85 25,36.091 23.65,34.741 23.65,29.922 24.825,28.747 24.825,23.12 27.3,20.645 27.3,13.125 v1@27.775,12.65
  Bottom Layer w0.15: v1@27.775,12.55 56.725,12.55 61.001,16.826 66.311,16.826 67.228,17.743 67.228,19.051 XP6.16@68.153,19.976
  other v1: 27.771,12.594
PD8: DD3.55 XP3.14 | length 48.5
  Top Layer w0.15: v1(39.348,53) 39.413,53 39.526,52.887 DD3.55@39.525,49.582 DD3.55@39.525,49.582
  Mid-Layer 2 w0.15: v1(39.348,53) 39.348,52.553 37.04,50.245 37.04,44.115 36.055,43.13 36.055,33.657 40.222,29.49 51.9,29.49 52.791,28.6 54.377,28.6 54.536,28.44 55.228,27.749 55.228,26.44 XP3.14@56.153,25.515
PD9: DD3.56 XP3.1 | length 62.5
  Top Layer w0.15: DD3.56@39.025,49.582 39.025,52.334 38.773,52.587 38.773,53.238 38.875,53.34 38.875,54.326 39.274,54.725 40.023,54.725 40.176,54.572
  Mid-Layer 2 w0.15: v1(40.301,54.286) 40.301,52.516 37.74,49.955 37.74,43.825 36.655,42.74 36.655,33.906 40.37,30.19 52.19,30.19 53.081,29.3 54.594,29.3 55.103,28.79 66.878,28.79 XP3.1@68.153,27.515
PD10: DD3.57 XP3.11 | length 51.3
  Top Layer w0.15: v1(38.3,53.575) 38.346,53.529 38.346,51.892 38.525,51.713 DD3.57@38.525,49.582
  Mid-Layer 2 w0.15: v1(38.3,53.575) 39.675,53.575 39.951,53.299 39.951,52.661 37.39,50.1 37.39,43.97 36.355,42.935 36.355,33.782 40.296,29.84 52.045,29.84 52.936,28.95 54.519,28.95 55.029,28.44 57.228,28.44 XP3.11@58.153,27.515
PD11: DD3.58 XP3.15 | length 44.2
  Top Layer w0.15: v1(37.638,52.417) 37.645,52.41 37.645,52.337 37.996,51.986 37.996,49.611 DD3.58@38.025,49.582
  Mid-Layer 2 w0.15: v1(37.638,52.417) 37.638,51.338 36.69,50.39 36.69,44.26 35.75,43.32 35.75,33.538 36.217,33.071 36.217,32.01 38.582,29.645 39.542,29.645 40.047,29.14 51.755,29.14 53.38,27.515 XP3.15@54.153,27.515
PD12: DD3.59 XP7.10 | length 60.8
  Top Layer w0.15: v1(30.774,44.847) 30.796,44.825 31.15,44.825 32.79,46.465 35.165,46.465 37.525,48.826 DD3.59@37.525,49.582
  Mid-Layer 2 w0.15: v1(30.774,44.847) 30.753,44.825 30.369,44.825 30.194,44.65 29.206,44.65 28.6,44.044 28.6,36.86 30.127,35.333 30.127,29.406 31.252,28.28 31.252,17.459 v1(31.55,17.162)
  Bottom Layer w0.15: v1(31.55,17.162) 31.55,17.213 31.638,17.301 33.749,17.301 35.175,15.875 46.72,15.875 48.175,17.33 48.175,18.956 XP7.10@49.195,19.976
PD13: DD3.60 XP7.12 | length 64.3
  Top Layer w0.15: v1(31.225,46.514) 31.663,46.514 31.964,46.815 35.02,46.815 37.025,48.821 DD3.60@37.025,49.582
  Mid-Layer 2 w0.15: v1(31.15,16.469) 31.15,16.549 30.925,16.774 30.925,28.113 29.777,29.261 29.777,35.188 28.3,36.665 28.3,44.169 29.131,45 29.711,45 v1(31.225,46.514)
  Bottom Layer w0.15: v1(31.15,16.469) 32.756,16.469 33.375,15.85 34.195,15.85 34.87,15.175 48.915,15.175 50.2,16.46 50.2,18.981 XP7.12@51.195,19.976
PD14: DD3.61 XP3.16 | length 45.2
  Top Layer w0.15: DD3.61@36.525,49.582 36.525,50.851 36.7,51.026 v1(36.7,51.95)
  Mid-Layer 2 w0.15: v1(36.7,51.95) 36.625,51.875 36.625,50.949 36.34,50.663 36.34,44.405 35.4,43.465 35.4,33.464 35.917,32.947 35.917,30.786 37.359,29.345 39.418,29.345 40.038,28.725 51.676,28.725 52.842,27.559 52.842,26.827 XP3.16@54.153,25.515
PD15: DD3.62 XP4.2 | length 42.1
  Top Layer w0.15: v1(35.99,51.335) 36.025,51.3 DD3.62@36.025,49.582
  Mid-Layer 2 w0.15: v1(35.99,51.335) 35.99,45.865 34.7,44.575 34.7,31.7 34.45,31.45 34.45,31.075 34.85,30.675 34.85,29.944 36.937,27.857 39.533,27.857 40.936,26.454 50.256,26.454 XP4.2@51.195,25.515
PE0: DD3.97 XP4.11 | length 39.3
  Top Layer w0.15: v1(22.975,37.402) 23.019,37.357 DD3.97@27.8,37.357
  Mid-Layer 2 w0.15: v1(22.975,37.402) 22.473,36.9 22.473,35.575 23.05,34.999 23.05,29.645 23.747,28.948 23.747,27.774 24.425,27.096 24.425,22.777 v1(24.476,22.726)
  Bottom Layer w0.15: v1(24.476,22.726) 24.795,23.045 35.719,23.045 38.705,26.032 39.711,26.032 XP4.11@41.195,27.515
PE1: DD3.98 XP4.5 | length 40.4
  Top Layer w0.15: v1(22.998,36.402) 24.013,36.402 24.468,36.857 DD3.98@27.8,36.857
  Mid-Layer 2 w0.15: v1(22.998,36.402) 22.998,35.475 23.35,35.123 23.35,29.769 24.262,28.857 24.262,28.002 v1(24.281,27.983)
  Bottom Layer w0.15: v1(24.281,27.983) 24.281,27.964 27.545,24.7 28.93,24.7 30.73,26.5 38.18,26.5 40.38,28.7 46.011,28.7 46.261,28.45 XP4.5@47.195,27.515
PE2: DD3.1 XP4.6 | length 38.5
  Top Layer w0.15: v1(26.131,31.9) 26.218,31.986 26.218,32.129 26.219,32.13 26.83,32.13 27.771,33.071 29.263,33.071 29.525,33.332 DD3.1@29.525,34.132
  Mid-Layer 2 w0.15: v1(26.131,31.9) 26.067,31.9 25.632,31.464 25.632,30.33 25.45,30.149 25.45,23.527 27.397,21.58 v1(27.556,21.58)
  Bottom Layer w0.15: v1(27.556,21.58) 35.288,21.58 38.508,24.8 39.1,24.8 40.741,26.441 45.66,26.441 46.47,25.63 47.081,25.63 XP4.6@47.195,25.515
PE3: DD3.2 XP4.9 | length 32.9
  Top Layer w0.15: v1(26.158,31.1) 26.182,31.125 26.249,31.125 27.857,32.733 29.542,32.733 30.025,33.215 DD3.2@30.025,34.132
  Mid-Layer 2 w0.15: v1(26.124,23.595) 26.124,23.629 25.75,24.002 25.75,30.024 26.051,30.326 26.051,31.013 26.07,31.013 v1(26.158,31.1)
  Bottom Layer w0.15: v1(26.124,23.595) 35.77,23.595 40.575,28.4 42.311,28.4 XP4.9@43.195,27.515
PE4: DD3.3 XP4.3 | length 32.8
  Top Layer w0.15: v1(27.852,27.687) 27.803,27.687 26.725,28.765 26.725,31.176 27.981,32.433 29.896,32.433 30.525,33.062 DD3.3@30.525,34.132
  Bottom Layer w0.15: v1(27.852,27.687) 27.952,27.687 28.165,27.475 31.05,27.475 31.325,27.2 37.89,27.2 39.99,29.3 47.252,29.3 49.037,27.515 XP4.3@49.195,27.515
